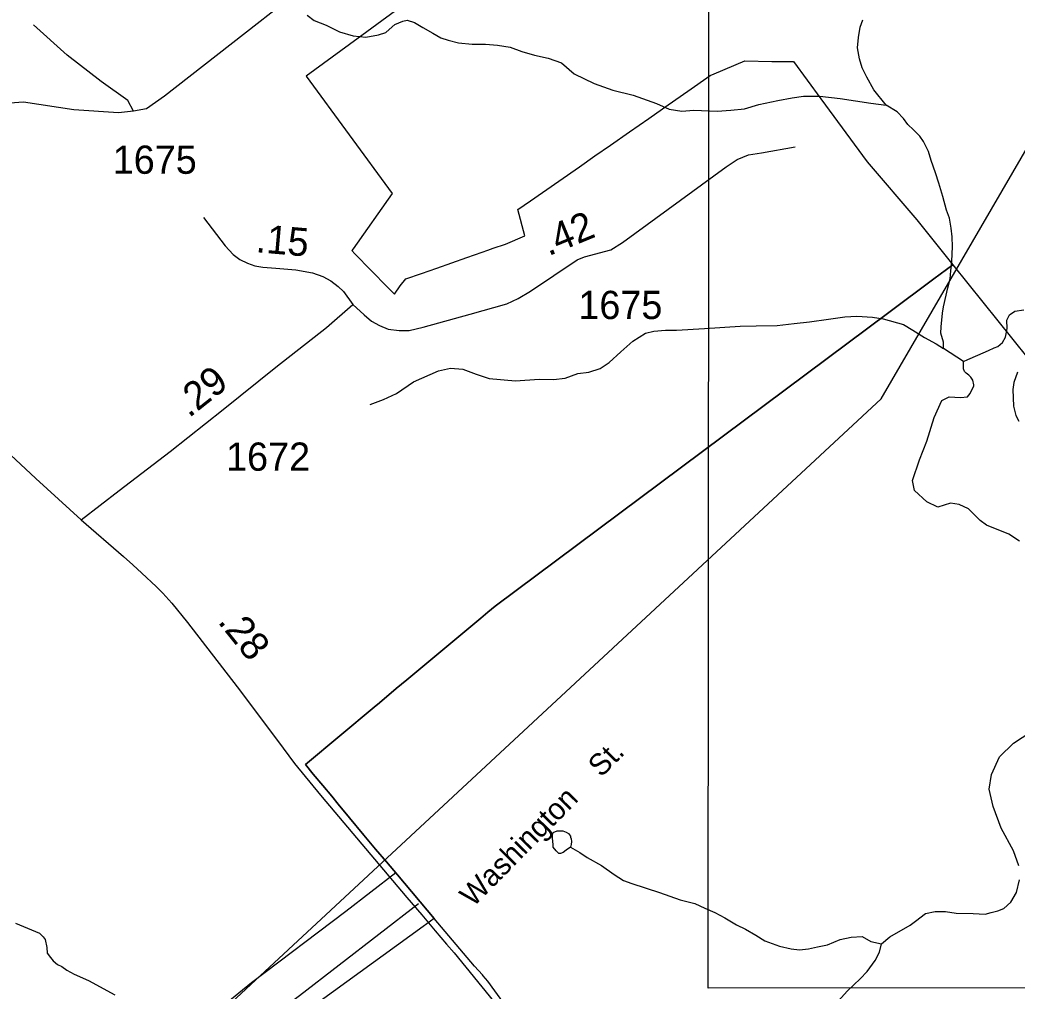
# Model space of a CAD drawing. Extents: x 2056842 to 2160602, y 826753 to 1016856.
# Drawn here: x 2082930 to 2087342, y 868296 to 872595 of the extents above; entities that cross this region are included whole.
import ezdxf

# ---------------------------------------------------------------- set-up
doc = ezdxf.new("R2010")
doc.units = 0
for name, color, linetype in [('Exist Boundary Political City Limit New', 7, 'Continuous'), ('Exist Hydrographic Creek Single Shore', 7, 'Continuous'), ('Exist Hydrographic Lake Shore', 7, 'Continuous'), ('Exist Hydrographic Misc Water Feature', 7, 'Continuous'), ('Exist Road Non-System Type 51', 7, 'Continuous'), ('Exist Road Non-System Type 51 Label', 7, 'Continuous'), ('Exist Road Primary NC Attributed', 7, 'Continuous'), ('Exist Road Primary NC Service Mileage Hundredths English Label', 7, 'Continuous'), ('Exist Road Secondary Mileage Hundredths English Label', 7, 'Continuous'), ('Exist Road Secondary Type 51 Attributed', 7, 'Continuous'), ('Exist Road Secondary Type 51 Number Label', 7, 'Continuous'), ('Exist Utilities Telephone Line', 7, 'Continuous'), ('Map Preparation Boundary City Limit Buffer Line', 7, 'Continuous'), ('Map Preparation Inset Cut Line', 7, 'Continuous')]:
    doc.layers.add(name, color=color, linetype=linetype)

msp = doc.modelspace()

# ---------------------------------------------------------------- linework, layer by layer
at = {"layer": 'Exist Boundary Political City Limit New'}
for points in [[(2085000, 872936.6), (2084465, 872541.6), (2084196.8, 872345.3), (2084577.4, 871827.1), (2084404.5, 871582), (2084398.2, 871573.7), (2084412.5, 871559.1), (2084484.5, 871485.6), (2084556.8, 871411.8), (2084587.2, 871380.6), (2084612.6, 871417.6), (2084638.2, 871448), (2084707.1, 871472.2), (2084774.1, 871495.8), (2084841.1, 871519.3)], [(2084841.1, 871519.3), (2084908.1, 871542.9), (2084975.1, 871566.4), (2085000, 871575.2), (2085024.6, 871583.8), (2085078.2, 871602.7), (2085164.5, 871638.9), (2085133.8, 871755.3), (2085189, 871793.8), (2085314.8, 871881.6), (2085405.4, 871944.8), (2085474.2, 871992.8), (2085542.8, 872040.6), (2085627.2, 872099.5), (2085712.5, 872159), (2085798.6, 872219.1), (2085886, 872280), (2085983.8, 872348.2), (2086001.2, 872355.6), (2086137.6, 872412.9), (2086256.6, 872411.3), (2086352.1, 872410), (2086473.1, 872245.6), (2086678.4, 871966.4), (2086898.6, 871709.4), (2087057.6, 871511.3)], [(2087057.6, 871511.3), (2086974.2, 871449), (2086775.2, 871300.4), (2085033.1, 870000), (2085000, 869972.7), (2084969.5, 869947.2), (2084642.5, 869674.2), (2084595.4, 869634.8), (2084521, 869572.7), (2084497.4, 869553), (2084193.4, 869299.2), (2084228, 869255.9), (2084270, 869206.6), (2084310.6, 869159), (2084338.9, 869123.8), (2084388.1, 869062.8), (2084452.4, 868986.4), (2084503.9, 868924.8), (2084551.4, 868867.9), (2084600.1, 868810.2), (2084762.4, 868618)], [(2084762.4, 868618), (2084600.1, 868810.2), (2084551.4, 868867.9), (2084503.9, 868924.8), (2084452.4, 868986.4), (2084388.1, 869062.8), (2084338.9, 869123.8), (2084310.6, 869159), (2084270, 869206.6), (2084228, 869255.9), (2084193.4, 869299.2), (2084497.4, 869553), (2084521, 869572.7), (2084595.4, 869634.8), (2084642.5, 869674.2), (2084969.5, 869947.2), (2085000, 869972.7), (2085033.1, 870000), (2086775.2, 871300.4), (2086974.2, 871449), (2087057.6, 871511.3)], [(2087057.6, 871511.3), (2087588.5, 870850.1), (2087746.9, 870815.1), (2087757.2, 870642.9), (2087769.2, 870444.5), (2087779.2, 870277.6), (2087796, 870000), (2087838.8, 869951.1), (2088183.9, 869931.5), (2088389.5, 869919.8), (2088541, 869698.1), (2088532.8, 869592.1), (2088500.6, 869460.6), (2088169.9, 869281.8), (2088101.9, 868845), (2088255.5, 868408.6), (2088615.6, 868299.1)], [(2084762.4, 868618), (2084714.8, 868581.4), (2083641.4, 867804.3)], [(2085416.8, 867765.6), (2085000, 868339.6), (2084979.8, 868363.7), (2084976.5, 868367.6), (2084940.9, 868406.5), (2084762.4, 868618)]]:
    msp.add_lwpolyline(points, dxfattribs=at)
at = {"layer": 'Exist Hydrographic Creek Single Shore'}
for points in [[(2084200.4, 872615.6), (2084232.2, 872591.8), (2084284.5, 872572), (2084344.6, 872542.2), (2084404.5, 872524.2), (2084460.4, 872518.6), (2084516.6, 872528.7), (2084548.4, 872538.9), (2084564.4, 872552.7), (2084588.4, 872574.6), (2084624.3, 872589.1), (2084644.2, 872593), (2084675.9, 872583.2), (2084712.2, 872561.1), (2084756.5, 872535.4), (2084792.2, 872515.4), (2084824.6, 872505.5), (2084870.5, 872493.7), (2084930.4, 872487.9), (2084990.3, 872488.1), (2085042.6, 872482.3), (2085098.6, 872474.6), (2085150.4, 872454.5), (2085206.6, 872438.7), (2085266.7, 872425.2), (2085326.8, 872405.1), (2085382.6, 872355.6), (2085470.9, 872313.8), (2085553, 872284), (2085643.2, 872262.1), (2085747.1, 872224.5), (2085803.1, 872199), (2085859.1, 872190.9), (2085911.4, 872195.1), (2086015.1, 872191.5), (2086075.4, 872195.4), (2086135.5, 872201.7), (2086199.3, 872220), (2086283.1, 872238.1), (2086347.1, 872250.3), (2086397, 872256.6), (2086469.3, 872257), (2086559.1, 872247.1), (2086695.3, 872225.6), (2086763.2, 872217.7)], [(2086762.9, 872217.6), (2086708.9, 872285.3), (2086676.6, 872341.5), (2086656.4, 872383.2), (2086644.5, 872423.2), (2086636.3, 872471.2), (2086640.2, 872517.1), (2086648, 872563.2), (2086659.8, 872595.1)], [(2087016.3, 871140.4), (2087016.2, 871168.7), (2087004.2, 871208.6), (2087006.1, 871236.5), (2087011.9, 871296.4), (2087015.8, 871324.5), (2087035.6, 871408.4), (2087045.3, 871448.6), (2087049.3, 871484.6), (2087053.1, 871526.5), (2087056.7, 871590.8), (2087054.7, 871634.8), (2087050.6, 871672.6), (2087042.6, 871716.7), (2087030.2, 871752.4), (2087014.1, 871812.5), (2086996, 871872.6), (2086981.8, 871918.5), (2086961.6, 871972.4), (2086949.6, 872012.3), (2086927.6, 872056.1), (2086911.3, 872080), (2086883.4, 872108.2), (2086859.3, 872132), (2086839.1, 872158), (2086810.9, 872187.8), (2086762.9, 872217.6)], [(2084479.5, 870892.6), (2084539.4, 870915.2), (2084595.6, 870941.1), (2084671.9, 870993.4), (2084781.8, 871040.9), (2084835.5, 871053.4), (2084890.5, 871048.4), (2084949.3, 871027.2), (2085006.9, 871008.2), (2085123.2, 870996.7), (2085226.9, 871005.3), (2085291.3, 871003.2), (2085342.8, 871009.6), (2085399, 871029.6), (2085447.1, 871035.6), (2085497, 871052), (2085536.6, 871078.1), (2085588.8, 871126.1), (2085642.4, 871172.4), (2085698.5, 871208.5), (2085734.4, 871216.9), (2085786.5, 871220.8), (2085834.5, 871221.2), (2085958.3, 871229.6), (2086116.4, 871239.6), (2086188.2, 871240.2), (2086280.5, 871242.4), (2086356.1, 871250.4), (2086424.2, 871258.7), (2086507.4, 871270.9), (2086579.8, 871280.9), (2086633.5, 871283.4), (2086702.3, 871278.4), (2086749.7, 871272.2), (2086839.7, 871247.2), (2086880.9, 871222.2), (2086932.1, 871188.7), (2086984.4, 871160.4), (2087016.4, 871140.6)], [(2083051.3, 868464.3), (2083065.5, 868444.3), (2083077.6, 868430.6), (2083095.8, 868414.5), (2083115.3, 868404.7), (2083137.6, 868388.7), (2083169.6, 868370.9), (2083233.8, 868342.9), (2083349.9, 868279.4)]]:
    msp.add_lwpolyline(points, dxfattribs=at)
at = {"layer": 'Exist Hydrographic Lake Shore'}
for points in [[(2087104.3, 871082.8), (2087124.5, 871091), (2087168.2, 871111.1), (2087216.2, 871131.1), (2087240.1, 871143.4), (2087256.3, 871149.3), (2087277.1, 871167.4), (2087290.8, 871191.1), (2087298.3, 871228.6), (2087297.1, 871266.1), (2087308.3, 871289.9), (2087332, 871304.9), (2087372, 871311.1)], [(2086975.9, 870835.3), (2087008.4, 870909.6), (2087040.9, 870925.9), (2087092.1, 870923.4), (2087123.1, 870926.9), (2087134.9, 870941.1), (2087150.7, 870974.9), (2087150.7, 870978.9), (2087146.6, 871000.9), (2087136.7, 871012.9), (2087128.7, 871023), (2087116.7, 871030.7), (2087108.7, 871038.8), (2087104.7, 871051), (2087104.6, 871062.8), (2087104.3, 871082.8)], [(2087343.3, 871036), (2087327, 870989.7), (2087323.3, 870958.5), (2087325.8, 870884.7), (2087335.8, 870843.4), (2087349.5, 870818.4)], [(2087353.2, 870287.3), (2087305.8, 870318.5), (2087207.1, 870358.8), (2087178.3, 870378.8), (2087127.1, 870430.1), (2087085.9, 870450.1), (2087047.1, 870456.3), (2086990.9, 870437.6), (2086942.2, 870461.3), (2086888.4, 870512.6), (2086879.7, 870556.3), (2086909.7, 870647.6), (2086942.2, 870730.1), (2086975.9, 870835.3)], [(2087349.5, 868850.1), (2087325.8, 868917.6), (2087272, 869017.6), (2087235.8, 869113.9), (2087218.3, 869190.1), (2087228.3, 869254.9), (2087264.5, 869333.7), (2087325.8, 869393.7), (2087440.7, 869468.7)], [(2086742.3, 868506), (2086779.7, 868536), (2086868.4, 868588.5), (2086892.4, 868606.3), (2086937.2, 868639), (2086979.7, 868649), (2087025.9, 868649), (2087072.1, 868641.5), (2087148, 868639.1), (2087200.1, 868637.4), (2087228.1, 868643.4), (2087256.2, 868651.7), (2087284, 868661.6), (2087314.5, 868690.3), (2087339.5, 868732.8), (2087353.2, 868788.8)], [(2086397.4, 867345.2), (2086366.2, 867411.5), (2086352.4, 867475.2), (2086349.8, 867544.9), (2086341.5, 867590.7), (2086327.4, 867634.1), (2086339.9, 867704.2), (2086381.2, 867790.4), (2086408.6, 867834.2), (2086426.1, 867876.7), (2086444.9, 867962.8), (2086468.6, 868070.3), (2086492.4, 868164.1), (2086517.3, 868215.4), (2086549.8, 868251.6), (2086592.3, 868296.6), (2086648.5, 868350.4), (2086678.5, 868383.5), (2086714.8, 868431), (2086733.5, 868468.5), (2086742.3, 868506)]]:
    msp.add_lwpolyline(points, dxfattribs=at)
at = {"layer": 'Exist Hydrographic Misc Water Feature'}
for points in [[(2087104.3, 871082.8), (2087016.3, 871140.4)], [(2085365.5, 868933.5), (2085346.3, 868919.4), (2085334, 868909.5), (2085322.3, 868905.2), (2085314.1, 868905.2), (2085302.2, 868917.2), (2085289.9, 868933.3), (2085289.9, 868945.4), (2085286, 868973.2), (2085285.8, 868989.5), (2085289.5, 868997.4), (2085307.9, 869005.2), (2085331.7, 869005.7), (2085347.7, 868999.5), (2085357.7, 868993.6), (2085365.5, 868981.5), (2085365.7, 868977.8), (2085369.4, 868969.5), (2085370, 868957.6), (2085369.6, 868945.5), (2085365.5, 868933.5)], [(2085365.5, 868933.5), (2085407.8, 868909.6), (2085440, 868888.1), (2085503.7, 868852.1), (2085559.9, 868812.3), (2085600.3, 868786.3), (2085637.8, 868772.6), (2085760.1, 868733.3), (2085852.1, 868699.5), (2085916.3, 868683.7), (2085960.6, 868663.6), (2086004.5, 868643.9), (2086048.4, 868619.8), (2086100.9, 868590), (2086140.4, 868570.2), (2086186.8, 868544.4), (2086226.6, 868518.5), (2086290.5, 868494.6), (2086343, 868483), (2086378.9, 868479.2), (2086418.7, 868483.3), (2086458.9, 868491.4), (2086503, 868501.4), (2086558.6, 868524.8), (2086608.6, 868534.8), (2086656, 868538.5), (2086694.8, 868516), (2086742.3, 868506)], [(2082910.1, 868596.7), (2083017.1, 868552.2), (2083033.1, 868536.4), (2083041.5, 868524.7), (2083049.5, 868488.5), (2083051.3, 868464.3)]]:
    msp.add_lwpolyline(points, dxfattribs=at)
at = {"layer": 'Exist Road Non-System Type 51'}
for points in [[(2085030.5, 873395.8), (2084451, 872946.1), (2083570.2, 872256.8), (2083490.4, 872201.7), (2083433.4, 872190.3)], [(2083433.4, 872190.3), (2083407.7, 872238.7), (2083289.9, 872322.4), (2083139.8, 872438.4), (2082989.7, 872573.4)], [(2083433.4, 872190.3), (2083365.9, 872183.6), (2083168.3, 872196.9), (2082946, 872231.1), (2082803.5, 872219.7), (2082670.5, 872193.1), (2082531.7, 872138), (2082023.4, 871872.7), (2081920.3, 871820.3)], [(2084593.6, 868819.8), (2084372.1, 868648), (2083954.7, 868332.1), (2083674.3, 868103.5), (2083702.3, 868046.3), (2083760.5, 868000.6), (2083799.9, 868002.7), (2084167.5, 868277), (2084694.1, 868683.5)]]:
    msp.add_lwpolyline(points, dxfattribs=at)
at = {"layer": 'Exist Road Primary NC Attributed'}
for points in [[(2082183.6, 871474.2), (2082457.6, 871132.9), (2082731, 870816.1), (2083000.6, 870565.7), (2083201.5, 870381.5)], [(2083201.5, 870381.5), (2083388.4, 870219.7), (2083429.8, 870182.8), (2083470.1, 870145.9), (2083532.8, 870087.7), (2083562.5, 870056.9), (2083601.6, 870013.8), (2083671, 869927.7), (2083892, 869642.3), (2084070.5, 869405.6), (2084144.4, 869303.2), (2084259.7, 869163.3), (2084642.4, 868710.1), (2084707.9, 868633.4), (2084767.2, 868562.3), (2084817.5, 868504.1), (2084851.1, 868465), (2085025.1, 868251.2)]]:
    msp.add_lwpolyline(points, dxfattribs=at)
at = {"layer": 'Exist Road Secondary Type 51 Attributed'}
for points in [[(2084403.8, 871335.5), (2084453.4, 871290), (2084486.2, 871261.1), (2084520.9, 871241.8), (2084559.5, 871226.3), (2084607.7, 871220.6), (2084652.1, 871220.6), (2084713.8, 871234.1), (2084922.1, 871291.9), (2085084.8, 871338.2), (2085134.9, 871361.3), (2085188.9, 871394.1), (2085395.4, 871532.9), (2085428.2, 871546.4), (2085544.2, 871577.8), (2085596.6, 871609.9), (2086054.4, 871945), (2086103.9, 871977), (2086153.5, 871997.4), (2086211.8, 872006.2), (2086360.7, 872033.3)], [(2083742.5, 871720), (2083838.9, 871594.6), (2083873.7, 871556.1), (2083902.6, 871534.9), (2083937.3, 871517.5), (2083970.1, 871505.9), (2084004.8, 871500.2), (2084062.7, 871496.3), (2084151.5, 871488.6), (2084224.8, 871475.1), (2084271.1, 871459.7), (2084305.8, 871440.4), (2084338.6, 871415.3), (2084361.7, 871392.2), (2084403.8, 871335.5)], [(2083201.5, 870381.5), (2083368.6, 870512), (2083595, 870685), (2083829.2, 870870.8), (2084062, 871058.4), (2084287.2, 871232.9), (2084403.8, 871335.5)]]:
    msp.add_lwpolyline(points, dxfattribs=at)
at = {"layer": 'Exist Utilities Telephone Line'}
msp.add_lwpolyline([(2070574.6, 855889.8), (2073540.2, 858741.1), (2079471.4, 864196.3), (2082575.1, 867047.6), (2086740, 870917.2), (2087764.9, 872677.4), (2089015.1, 875921.4), (2089705.6, 877143.4), (2092053.4, 881391.2), (2094430.2, 885697.2), (2096843.4, 888330.3), (2097766.5, 889363.1), (2100637.6, 891101.5), (2103123.5, 892599.9), (2104820.7, 893625.5), (2107244.8, 895109.3), (2108287.8, 895378.4), (2108625.8, 895633), (2109723.4, 896782.2), (2110232.2, 897204.1), (2110707.5, 898076.3)], dxfattribs=at)
at = {"layer": 'Map Preparation Boundary City Limit Buffer Line'}
for points in [[(2085000, 872936.6), (2084465, 872541.6), (2084196.8, 872345.3), (2084577.4, 871827.1), (2084404.5, 871582), (2084398.2, 871573.7), (2084412.5, 871559.1), (2084484.5, 871485.6), (2084556.8, 871411.8), (2084587.2, 871380.6), (2084612.6, 871417.6), (2084638.2, 871448), (2084707.1, 871472.2), (2084774.1, 871495.8), (2084841.1, 871519.3)], [(2084841.1, 871519.3), (2084908.1, 871542.9), (2084975.1, 871566.4), (2085000, 871575.2), (2085024.6, 871583.8), (2085078.2, 871602.7), (2085164.5, 871638.9), (2085133.8, 871755.3), (2085189, 871793.8), (2085314.8, 871881.6), (2085405.4, 871944.8), (2085474.2, 871992.8), (2085542.8, 872040.6), (2085627.2, 872099.5), (2085712.5, 872159), (2085798.6, 872219.1), (2085886, 872280), (2085983.8, 872348.2), (2086001.2, 872355.6), (2086137.6, 872412.9), (2086256.6, 872411.3), (2086352.1, 872410), (2086473.1, 872245.6), (2086678.4, 871966.4), (2086898.6, 871709.4), (2087057.6, 871511.3)], [(2087057.6, 871511.3), (2086974.2, 871449), (2086775.2, 871300.4), (2085033.1, 870000), (2085000, 869972.7), (2084969.5, 869947.2), (2084642.5, 869674.2), (2084595.4, 869634.8), (2084521, 869572.7), (2084497.4, 869553), (2084193.4, 869299.2), (2084228, 869255.9), (2084270, 869206.6), (2084310.6, 869159), (2084338.9, 869123.8), (2084388.1, 869062.8), (2084452.4, 868986.4), (2084503.9, 868924.8), (2084551.4, 868867.9), (2084600.1, 868810.2), (2084762.4, 868618)], [(2084762.4, 868618), (2084600.1, 868810.2), (2084551.4, 868867.9), (2084503.9, 868924.8), (2084452.4, 868986.4), (2084388.1, 869062.8), (2084338.9, 869123.8), (2084310.6, 869159), (2084270, 869206.6), (2084228, 869255.9), (2084193.4, 869299.2), (2084497.4, 869553), (2084521, 869572.7), (2084595.4, 869634.8), (2084642.5, 869674.2), (2084969.5, 869947.2), (2085000, 869972.7), (2085033.1, 870000), (2086775.2, 871300.4), (2086974.2, 871449), (2087057.6, 871511.3)], [(2087057.6, 871511.3), (2087588.5, 870850.1), (2087746.9, 870815.1), (2087757.2, 870642.9), (2087769.2, 870444.5), (2087779.2, 870277.6), (2087796, 870000), (2087838.8, 869951.1), (2088183.9, 869931.5), (2088389.5, 869919.8), (2088541, 869698.1), (2088532.8, 869592.1), (2088500.6, 869460.6), (2088169.9, 869281.8), (2088101.9, 868845), (2088255.5, 868408.6), (2088615.6, 868299.1)], [(2084762.4, 868618), (2084714.8, 868581.4), (2083641.4, 867804.3)], [(2085416.8, 867765.6), (2085000, 868339.6), (2084979.8, 868363.7), (2084976.5, 868367.6), (2084940.9, 868406.5), (2084762.4, 868618)]]:
    msp.add_lwpolyline(points, dxfattribs=at)
at = {"layer": 'Map Preparation Inset Cut Line'}
msp.add_lwpolyline([(2059276.8, 845851.8), (2104036.2, 845851.8), (2104036.2, 868310.8), (2085975.1, 868308.6), (2085982, 877260.1), (2059276.8, 877260.1), (2059276.8, 845851.8)], dxfattribs=at)

# ---------------------------------------------------------------- texts
at = {"layer": 'Exist Road Non-System Type 51 Label'}
for s, p in [('St.', (2085501.9, 869238.8)), ('Washington', (2084935, 868664.7))]:
    msp.add_text(s, height=95, rotation=45.3595, dxfattribs=at).set_placement(p)
at = {"layer": 'Exist Road Primary NC Service Mileage Hundredths English Label'}
msp.add_text('.28', height=125, rotation=308.7427, dxfattribs=at).set_placement((2083802.5, 869930.1))
at = {"layer": 'Exist Road Secondary Mileage Hundredths English Label'}
for s, rotation, p in [('.42', 22.3703, (2085268.5, 871548.3)), ('.15', 355.0323, (2083971.2, 871567)), ('.29', 38.437, (2083678.2, 870830.8))]:
    msp.add_text(s, height=125, rotation=rotation, dxfattribs=at).set_placement(p)
at = {"layer": 'Exist Road Secondary Type 51 Number Label'}
for s, p in [('1675', (2083340.7, 871913.6)), ('1675', (2085400.8, 871270.7)), ('1672', (2083842.1, 870599.3))]:
    msp.add_text(s, height=125, dxfattribs=at).set_placement(p)

doc.saveas('drawing.dxf')
